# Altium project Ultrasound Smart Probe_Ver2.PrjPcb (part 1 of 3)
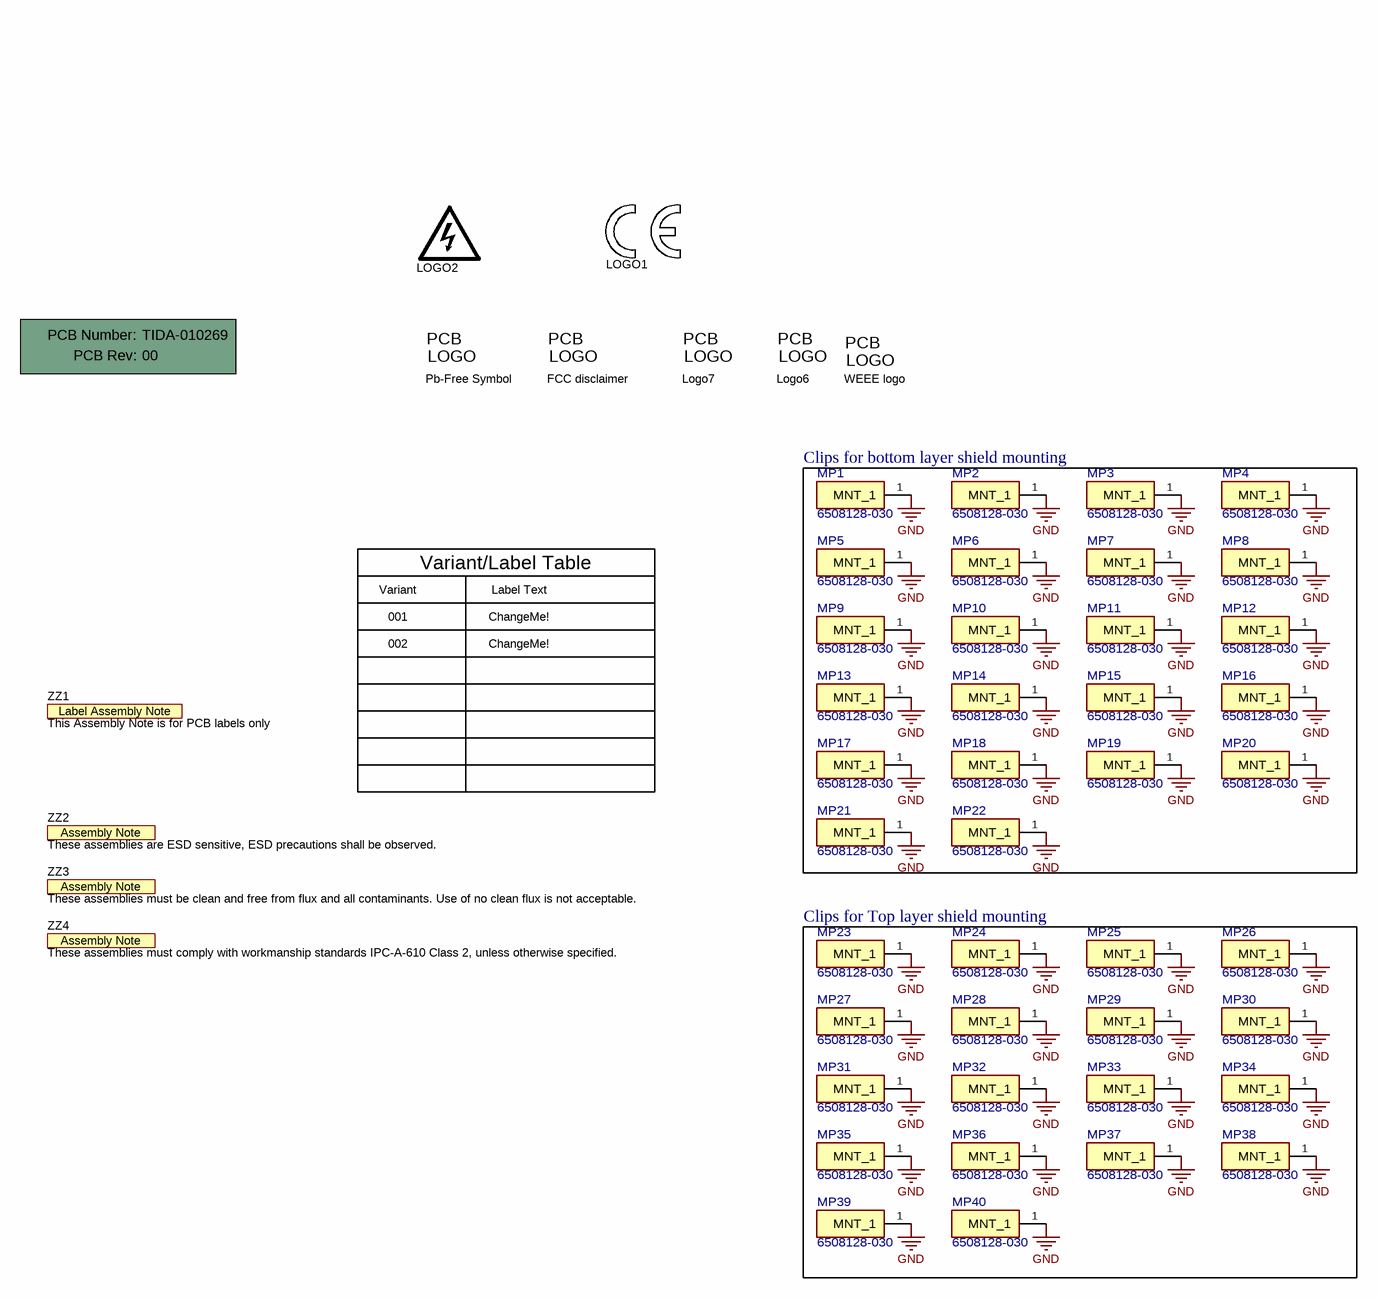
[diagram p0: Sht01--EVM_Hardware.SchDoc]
CopyrightYear: 2023; PCB_Layout: Bill.Xu; PCB_Rev: 00; PRJ_Customer: Public Release; PRJ_Engineer: Bill. Xu; PRJ_Number: TIDA-010269; PRJ_Title: Smart Probe Power Supply; SCH_Rev: 00; TechSupport: http://www.ti.com/support; TID: TIDA-010269
7 sheets, 486 parts. Net scope: flat (ports and power ports of the same name join across sheets).
Board file: TIDA-010269.PcbDoc
Sheets:
  Sht01--EVM_Hardware.SchDoc
  Sht02--Input Output Connector.SchDoc
  Sht03--Efuse_Power on-Off Controller.SchDoc
  Sht04--FPGA Power Supply.SchDoc
  Sht05--TX-RX Supply 1.8V and 1.15V.SchDoc
  Sht06--TX Supply +5V and -5V.SchDoc
  Sht07--High Voltage Power Supply.SchDoc

## Sheet Sht01--EVM_Hardware.SchDoc: Hardware
size 431 x 279 mm; Date: Not shown in title block; ApprovedBy: Not shown in title block; CheckedBy: Not shown in title block; Author: Not shown in title block; CompanyName: Not shown in title block; DrawnBy: Bill.Xu; Engineer: Bill.Xu; Organization: Not shown in title block; Address1: Not shown in title block; Address2: Not shown in title block; Address3: Not shown in title block; Address4: Not shown in title block; DocumentNumber: 1; Revision: Use project parameter SCH_Rev; SheetNumber: 1; SheetTotal: 7; PageSetup: Record=PageOptions¦CenterHorizontal=True¦CenterVertical=True¦PrintScale=1.00¦XCorrection=1.00¦YCorrection=1.00¦PrintKind=0¦BorderSize=5000000¦LeftOffset=0¦BottomOffset=0¦Orientation=2¦PaperLength=1000¦PaperWidth=1000¦Scale=100¦PaperSource=15¦PrintQuality=600¦MediaType=1¦DitherType=10¦PaperKind=Letter¦PrintScaleMode=1

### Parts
!PCB1  Printed Circuit Board  (value not drawn)  (mechanical)
LOGO1  CE Mark  [TI_Stacked_Overlay_Small]  (value not drawn)  (no BOM)
LOGO2  DANGER HIGH VOLTAGE  [CE_Mark_5mm]  (value not drawn)  (no BOM)
Logo3  Pb-Free Symbol  [FCC_disclaimer]  (no BOM)
Logo4  FCC disclaimer  [WEEE_Minimum]  (no BOM)
Logo5  WEEE logo  [WEEE_Minimum]  (no BOM)
Logo6  ESD Susceptible  [ESD_Overlay_Small]  (value not drawn)  (no BOM)
Logo7  Texas Instruments  [TI_Stacked_Overlay_Small]  (value not drawn)  (no BOM)
MP1  6508128-030  [0-MFG]
MP2  6508128-030  [0-MFG]
MP3  6508128-030  [0-MFG]
MP4  6508128-030  [0-MFG]
MP5  6508128-030  [0-MFG]
MP6  6508128-030  [0-MFG]
MP7  6508128-030  [0-MFG]
MP8  6508128-030  [0-MFG]
MP9  6508128-030  [0-MFG]
MP10  6508128-030  [0-MFG]
MP11  6508128-030  [0-MFG]
MP12  6508128-030  [0-MFG]
MP13  6508128-030  [0-MFG]
MP14  6508128-030  [0-MFG]
MP15  6508128-030  [0-MFG]
MP16  6508128-030  [0-MFG]
MP17  6508128-030  [0-MFG]
MP18  6508128-030  [0-MFG]
MP19  6508128-030  [0-MFG]
MP20  6508128-030  [0-MFG]
MP21  6508128-030  [0-MFG]
MP22  6508128-030  [0-MFG]
MP23  6508128-030  [0-MFG]
MP24  6508128-030  [0-MFG]
MP25  6508128-030  [0-MFG]
MP26  6508128-030  [0-MFG]
MP27  6508128-030  [0-MFG]
MP28  6508128-030  [0-MFG]
MP29  6508128-030  [0-MFG]
MP30  6508128-030  [0-MFG]
MP31  6508128-030  [0-MFG]
MP32  6508128-030  [0-MFG]
MP33  6508128-030  [0-MFG]
MP34  6508128-030  [0-MFG]
MP35  6508128-030  [0-MFG]
MP36  6508128-030  [0-MFG]
MP37  6508128-030  [0-MFG]
MP38  6508128-030  [0-MFG]
MP39  6508128-030  [0-MFG]
MP40  6508128-030  [0-MFG]
ZZ1  This Assembly Note is for PCB labels only  [AssemblyNoteLabel]  (no BOM)
ZZ2  These assemblies are ESD sensitive, ESD precautions shall be observed.  [AssemblyNote]  (no BOM)
ZZ3  These assemblies must be clean and free from flux and all contaminants. Use of no clean flux is not acceptable.  [AssemblyNote]  (no BOM)
ZZ4  These assemblies must comply with workmanship standards IPC-A-610 Class 2, unless otherwise specified.  [AssemblyNote]  (no BOM)

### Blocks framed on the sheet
Clips for bottom layer shield mounting: MP1-MP22
Clips for Top layer shield mounting: MP23-MP40

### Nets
GND: MP1.1(MNT_1) MP2.1(MNT_1) MP3.1(MNT_1) MP4.1(MNT_1) MP5.1(MNT_1) MP6.1(MNT_1) MP7.1(MNT_1) MP8.1(MNT_1) MP9.1(MNT_1) MP10.1(MNT_1) MP11.1(MNT_1) MP12.1(MNT_1) MP13.1(MNT_1) MP14.1(MNT_1) MP15.1(MNT_1) MP16.1(MNT_1) MP17.1(MNT_1) MP18.1(MNT_1) MP19.1(MNT_1) MP20.1(MNT_1) MP21.1(MNT_1) MP22.1(MNT_1) MP23.1(MNT_1) MP24.1(MNT_1) MP25.1(MNT_1) MP26.1(MNT_1) MP27.1(MNT_1) MP28.1(MNT_1) MP29.1(MNT_1) MP30.1(MNT_1) MP31.1(MNT_1) MP32.1(MNT_1) MP33.1(MNT_1) MP34.1(MNT_1) MP35.1(MNT_1) MP36.1(MNT_1) MP37.1(MNT_1) MP38.1(MNT_1) MP39.1(MNT_1) MP40.1(MNT_1)

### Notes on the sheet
- Variant/Label Table
- Variant
- 001
- 002
- Label Text
- ChangeMe!

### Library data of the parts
!PCB1 = PCB: Manufacturer: Any; PartNumber: TIDA-010269; SymbolCreator: a0412235
LOGO1 = CE Mark: SymbolCreator: a0412235
LOGO2 = IEC_HighVoltage: IEC 61010-1 High Voltage Warning; SymbolCreator: a0412235
Logo3 = Pb-Free: SymbolCreator: a0412235
Logo4 = FCC_disclaimer: SymbolCreator: a0412235
Logo5 = CMP-0074769-3: Manufacturer: Texas Instruments; Alternate Manufacturer: None; CompType: IC; AEC Category: Q200
Logo6 = ESD_Susceptible: ESD Susceptible Symbol; SymbolCreator: a0412235
Logo7 = TI_Logo: Texas Instrument Corporate Signature; SymbolCreator: a0412235
MP1-MP40 = CMP-0037144-1: SHIELD (T0.3) CAN CLIP L6.50*W0.8*H1.28mm; Manufacturer: Texas Instruments; SizeZ_mm: 1.38mm
ZZ1 = AssemblyNoteLabel: SymbolCreator: a0412235
ZZ2-ZZ4 = AssemblyNote: SymbolCreator: codlsc

## Sheet Sht02--Input Output Connector.SchDoc: Input Output Connectors
size 431 x 279 mm; Date: Not shown in title block; ApprovedBy: Not shown in title block; CheckedBy: Not shown in title block; Author: Not shown in title block; CompanyName: Not shown in title block; DrawnBy: Bill.Xu; Engineer: Bill.Xu; Organization: Not shown in title block; Address1: Not shown in title block; Address2: Not shown in title block; Address3: Not shown in title block; Address4: Not shown in title block; DocumentNumber: 1; Revision: Use project parameter SCH_Rev; SheetNumber: 2; SheetTotal: 7; PageSetup: Record=PageOptions¦CenterHorizontal=True¦CenterVertical=True¦PrintScale=1.00¦XCorrection=1.00¦YCorrection=1.00¦PrintKind=0¦BorderSize=5000000¦LeftOffset=0¦BottomOffset=0¦Orientation=2¦PaperLength=1000¦PaperWidth=1000¦Scale=100¦PaperSource=15¦PrintQuality=600¦MediaType=1¦DitherType=10¦PaperKind=Letter¦PrintScaleMode=1
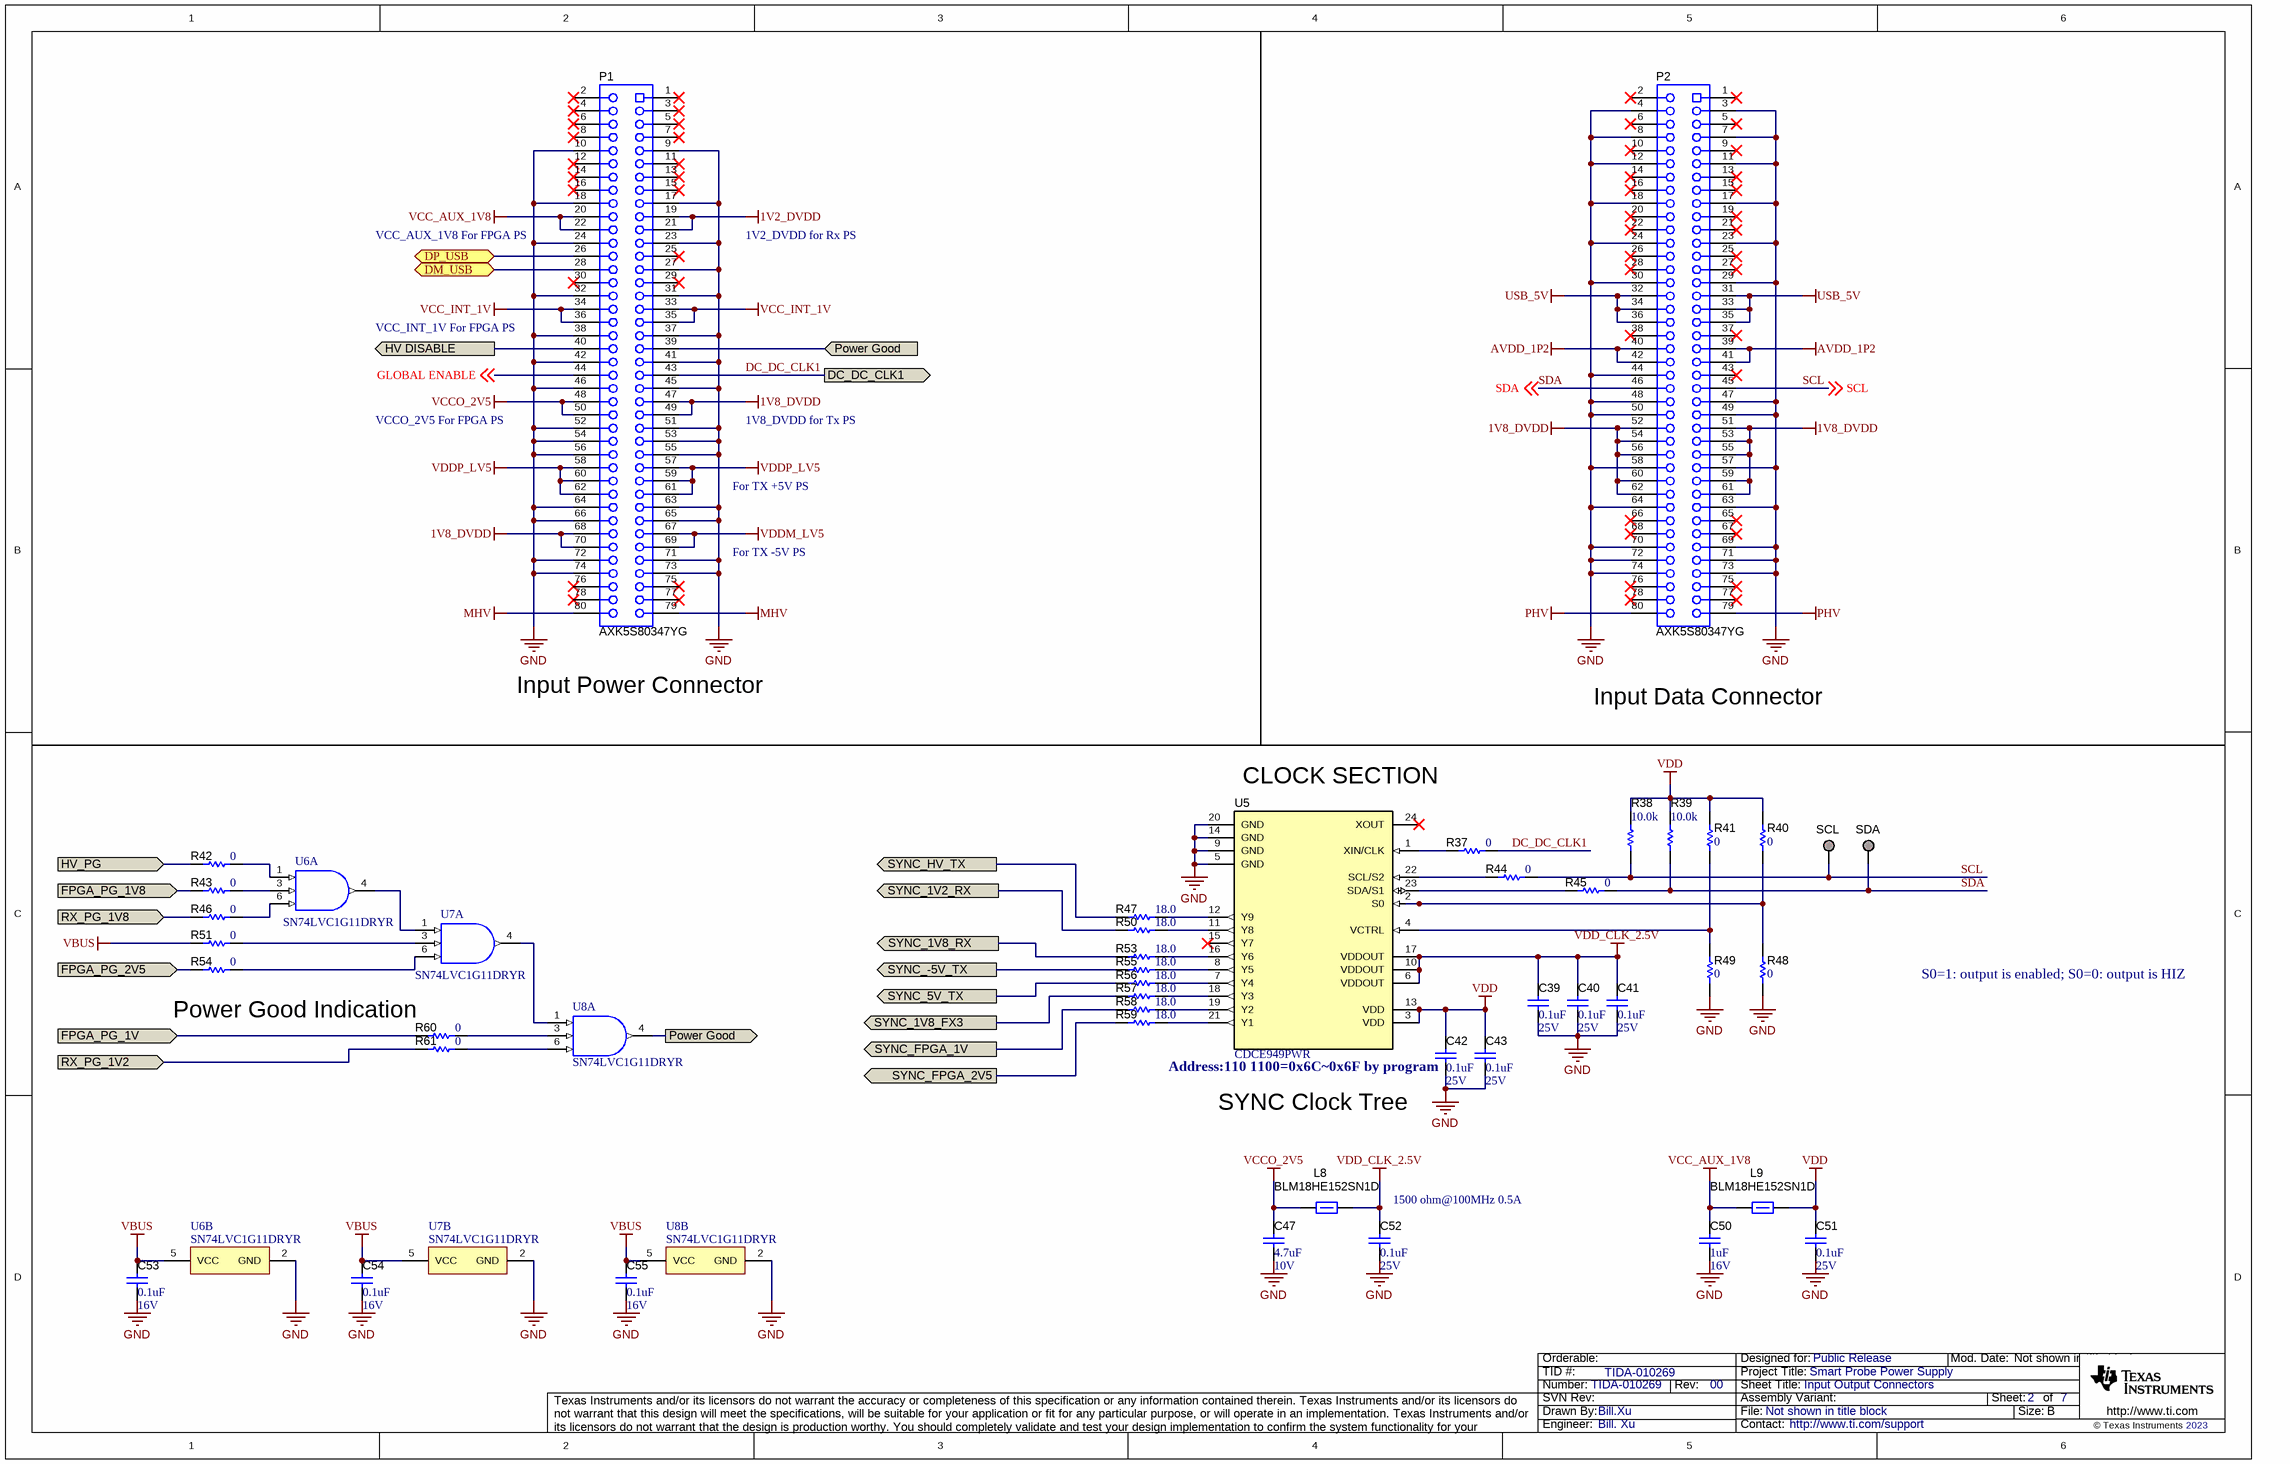
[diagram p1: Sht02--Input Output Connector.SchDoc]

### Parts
C39  VDC_V: 25V  ValueDisplayed: 0.1uF  [0402]  (hidden comment: GRM155R61E104KA87D)
C40  VDC_V: 25V  ValueDisplayed: 0.1uF  [0402]  (hidden comment: GRM155R61E104KA87D)
C41  VDC_V: 25V  ValueDisplayed: 0.1uF  [0402]  (hidden comment: GRM155R61E104KA87D)
C42  VDC_V: 25V  ValueDisplayed: 0.1uF  [0402]  (hidden comment: GRM155R61E104KA87D)
C43  VDC_V: 25V  ValueDisplayed: 0.1uF  [0402]  (hidden comment: GRM155R61E104KA87D)
C47  VDC_V: 10V  ValueDisplayed: 4.7uF  [0603]  (hidden comment: GRM188R61A475MAAJ)
C50  VDC_V: 16V  ValueDisplayed: 1uF  [0402]  (hidden comment: C1005X6S1C105K050BC)
C51  VDC_V: 25V  ValueDisplayed: 0.1uF  [0402]  (hidden comment: GRM155R61E104KA87D)
C52  VDC_V: 25V  ValueDisplayed: 0.1uF  [0402]  (hidden comment: GRM155R61E104KA87D)
C53  VDC_V: 16V  ValueDisplayed: 0.1uF  [0201_033]  (hidden comment: C0603X6S1C104K030BC)
C54  VDC_V: 16V  ValueDisplayed: 0.1uF  [0201_033]  (hidden comment: C0603X6S1C104K030BC)
C55  VDC_V: 16V  ValueDisplayed: 0.1uF  [0201_033]  (hidden comment: C0603X6S1C104K030BC)
L8  BLM18HE152SN1D  [0603]
L9  BLM18HE152SN1D  [0603]
P1  AXK5S80347YG  [Panasonic_AXK5S80347Y]
P2  AXK5S80347YG  [Panasonic_AXK5S80347Y]
R37  ValueDisplayed: 0  [0201]  (hidden comment: CRCW02010000Z0ED)
R38  ValueDisplayed: 10.0k  [0201]  (hidden comment: RC0201FS-7D10KL)
R39  ValueDisplayed: 10.0k  [0201]  (hidden comment: RC0201FS-7D10KL)
R40  ValueDisplayed: 0  [0201]  (hidden comment: CRCW02010000Z0ED)
R41  ValueDisplayed: 0  [0201]  (hidden comment: CRCW02010000Z0ED)
R42  ValueDisplayed: 0  [0201]  (hidden comment: CRCW02010000Z0ED)
R43  ValueDisplayed: 0  [0201]  (hidden comment: CRCW02010000Z0ED)
R44  ValueDisplayed: 0  [0201]  (hidden comment: CRCW02010000Z0ED)
R45  ValueDisplayed: 0  [0201]  (hidden comment: CRCW02010000Z0ED)
R46  ValueDisplayed: 0  [0201]  (hidden comment: CRCW02010000Z0ED)
R47  ValueDisplayed: 18.0  [0201]  (hidden comment: RC0201FR-0718RL)
R48  ValueDisplayed: 0  [0201]  (hidden comment: CRCW02010000Z0ED)
R49  ValueDisplayed: 0  [0201]  (hidden comment: CRCW02010000Z0ED)
R50  ValueDisplayed: 18.0  [0201]  (hidden comment: RC0201FR-0718RL)
R51  ValueDisplayed: 0  [0201]  (hidden comment: CRCW02010000Z0ED)
R53  ValueDisplayed: 18.0  [0201]  (hidden comment: RC0201FR-0718RL)
R54  ValueDisplayed: 0  [0201]  (hidden comment: CRCW02010000Z0ED)
R55  ValueDisplayed: 18.0  [0201]  (hidden comment: RC0201FR-0718RL)
R56  ValueDisplayed: 18.0  [0201]  (hidden comment: RC0201FR-0718RL)
R57  ValueDisplayed: 18.0  [0201]  (hidden comment: RC0201FR-0718RL)
R58  ValueDisplayed: 18.0  [0201]  (hidden comment: RC0201FR-0718RL)
R59  ValueDisplayed: 18.0  [0201]  (hidden comment: RC0201FR-0718RL)
R60  ValueDisplayed: 0  [0201]  (hidden comment: CRCW02010000Z0ED)
R61  ValueDisplayed: 0  [0201]  (hidden comment: CRCW02010000Z0ED)
SCL  TESTPOINT  [TESTPOINT]  (value not drawn)  (no BOM)
SDA  TESTPOINT  [TESTPOINT]  (value not drawn)  (no BOM)
U5  CDCE949PWR  [PW0024A_N]
U6  SN74LVC1G11DRYR  [DRY0006A]  (parts A,B of 2)
U7  SN74LVC1G11DRYR  [DRY0006A]  (parts A,B of 2)
U8  SN74LVC1G11DRYR  [DRY0006A]  (parts A,B of 2)

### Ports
DC_DC_CLK1 (out), DM_USB (bidir), DP_USB (bidir), FPGA_PG_1V8 (in), FPGA_PG_1V (in), FPGA_PG_2V5 (in), HV DISABLE (out), HV_PG (in), Power Good (in), Power Good (out), RX_PG_1V2 (in), RX_PG_1V8 (in), SYNC_1V2_RX (out), SYNC_1V8_FX3 (out), SYNC_1V8_RX (out), SYNC_5V_TX (out), SYNC_-5V_TX (out), SYNC_FPGA_1V (out), SYNC_FPGA_2V5 (out), SYNC_HV_TX (out)

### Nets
1V2_DVDD: P1.19 P1.21
1V8_DVDD: P1.47 P1.49 P1.68 P1.70 P2.51 P2.52 P2.53 P2.54 P2.55 P2.56 P2.59 P2.60 P2.61 P2.62
AVDD_1P2: P2.39 P2.40 P2.41 P2.42
GND: C39.2 C40.2 C41.2 C42.2 C43.2 C47.2 C50.2 C51.2 C52.2 C53.2 C54.2 C55.2 P1.9 P1.10 P1.17 P1.18 P1.23 P1.24 P1.27 P1.31 P1.32 P1.37 P1.38 P1.41 P1.42 P1.45 P1.46 P1.51 P1.52 P1.53 P1.54 P1.55 P1.56 P1.63 P1.64 P1.65 P1.66 P1.71 P1.72 P1.73 P1.74 P2.3 P2.4 P2.7 P2.8 P2.11 P2.12 P2.17 P2.18 P2.23 P2.24 P2.29 P2.30 P2.44 P2.47 P2.48 P2.49 P2.50 P2.57 P2.58 P2.63 P2.64 P2.69 P2.70 P2.71 P2.72 P2.73 P2.74 R48.2 R49.2 U5.5(GND) U5.9(GND) U5.14(GND) U5.20(GND) U6.2(GND) U7.2(GND) U8.2(GND)
MHV: P1.79 P1.80
PHV: P2.79 P2.80
USB_5V: P2.31 P2.32 P2.33 P2.34 P2.35 P2.36
VBUS: C53.1 C54.1 C55.1 R51.1 U6.5(VCC) U7.5(VCC) U8.5(VCC)
VCC_AUX_1V8: C50.1 L9.1 P1.20 P1.22
VCC_INT_1V: P1.33 P1.34 P1.35 P1.36
VCCO_2V5: C47.1 L8.1 P1.48 P1.50
VDD: C42.1 C43.1 C51.1 L9.2 R38.2 R39.2 R40.2 R41.2 U5.3(VDD) U5.13(VDD)
VDD_CLK_2.5V: C39.1 C40.1 C41.1 C52.1 L8.2 U5.6(VDDOUT) U5.10(VDDOUT) U5.17(VDDOUT)
VDDM_LV5: P1.67 P1.69
VDDP_LV5: P1.57 P1.58 P1.59 P1.60 P1.61 P1.62
DC_DC_CLK1: P1.43 R37.2 ; port DC_DC_CLK1
DM_USB: P1.28 ; port DM_USB
DP_USB: P1.26 ; port DP_USB
FPGA_PG_1V: R60.1 ; port FPGA_PG_1V
FPGA_PG_1V8: R43.1 ; port FPGA_PG_1V8
FPGA_PG_2V5: R54.1 ; port FPGA_PG_2V5
GLOBAL ENABLE: P1.44 ; off-sheet GLOBAL ENABLE
HV DISABLE: P1.40 ; port HV DISABLE
HV_PG: R42.1 ; port HV_PG
Power Good: P1.39 U8.4(Y) ; port Power Good
RX_PG_1V2: R61.1 ; port RX_PG_1V2
RX_PG_1V8: R46.1 ; port RX_PG_1V8
SCL: P2.45 R38.1 R44.2 SCL.1 ; off-sheet SCL
SDA: P2.46 R39.1 R45.2 SDA.1 ; off-sheet SDA
SYNC_1V2_RX: R50.1 ; port SYNC_1V2_RX
SYNC_1V8_FX3: R57.1 ; port SYNC_1V8_FX3
SYNC_1V8_RX: R53.1 ; port SYNC_1V8_RX
SYNC_5V_TX: R56.1 ; port SYNC_5V_TX
SYNC_-5V_TX: R55.1 ; port SYNC_-5V_TX
SYNC_FPGA_1V: R58.1 ; port SYNC_FPGA_1V
SYNC_FPGA_2V5: R59.1 ; port SYNC_FPGA_2V5
SYNC_HV_TX: R47.1 ; port SYNC_HV_TX
NetR37_1: R37.1 U5.1(XIN/CLK)
NetR40_1: R40.1 R48.1 U5.2(S0)
NetR41_1: R41.1 R49.1 U5.4(VCTRL)
NetR42_2: R42.2 U6.1(A)
NetR43_2: R43.2 U6.3(B)
NetR44_1: R44.1 U5.22(SCL/S2)
NetR45_1: R45.1 U5.23(SDA/S1)
NetR46_2: R46.2 U6.6(C)
NetR47_2: R47.2 U5.12(Y9)
NetR50_2: R50.2 U5.11(Y8)
NetR51_2: R51.2 U7.3(B)
NetR53_2: R53.2 U5.16(Y6)
NetR54_2: R54.2 U7.6(C)
NetR55_2: R55.2 U5.8(Y5)
NetR56_2: R56.2 U5.7(Y4)
NetR57_2: R57.2 U5.18(Y3)
NetR58_2: R58.2 U5.19(Y2)
NetR59_2: R59.2 U5.21(Y1)
NetR60_2: R60.2 U8.3(B)
NetR61_2: R61.2 U8.6(C)
NetU6_4: U6.4(Y) U7.1(A)
NetU7_4: U7.4(Y) U8.1(A)

Not connected (* = marked no-connect by the designer): P1 1* 2* 3* 4* 5* 6* 7* 8* 11* 12* 13* 14* 15* 16* 25* 29* 30* 75* 76* 77* 78*; P2 1* 2* 5* 6* 9* 10* 13* 14* 15* 16* 19* 20* 21* 22* 25* 26* 27* 28* 37* 38* 43* 65* 66* 67* 68* 75* 76* 77* 78*; U5 15(Y7)* 24(XOUT)*

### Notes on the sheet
- VCC_AUX_1V8 For FPGA PS
- 1V2_DVDD for Rx PS
- VCC_INT_1V For FPGA PS
- VCCO_2V5 For FPGA PS
- 1V8_DVDD for Tx PS
- For TX +5V PS
- For TX -5V PS
- Input Power Connector
- Input Data Connector
- (near U5) CLOCK SECTION
- Power Good Indication
- S0=1: output is enabled; S0=0: output is HIZ
- (near C42) Address:110 1100=0x6C~0x6F by program
- SYNC Clock Tree
- (near C52) 1500 ohm@100MHz 0.5A

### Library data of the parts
C39 C40 C43 C51 C52 = CMP-0006607-1: CAP, CERM, 0.1 uF, 25 V, +/- 10%, X5R, 0402; Manufacturer: MuRata; TaMin_C: -55°C; Polarized: N; SizeAreaWB_mm2: 3; Value1: Unknown; U/M: EA; Value: 0.1uF; TaMax_C: 85°C; SizeZ_mm: 0.6; SizeX_mm: 1; SizeY_mm: 0.5; Cap_F: 100nF; AEC Category: Q200
C41 C42 = CMP-0006607-2: CAP, CERM, 0.1 uF, 25 V, +/- 10%, X5R, 0402; Manufacturer: MuRata; TaMin_C: -55°C; Polarized: N; SizeAreaWB_mm2: 3; Value1: Unknown; U/M: EA; Value: 0.1uF; TaMax_C: 85°C; SizeZ_mm: 0.6; SizeX_mm: 1; SizeY_mm: 0.5; Cap_F: 100nF; AEC Category: Q200
C47 = CMP-0007329-4: CAP, CERM, 4.7 uF, 10 V, +/- 20%, X5R, 0603; Manufacturer: MuRata; TaMin_C: -55°C; Polarized: N; SizeAreaWB_mm2: 4.68; Value1: Unknown; U/M: EA; Value: 4.7uF; TaMax_C: 85°C; SizeZ_mm: 1; SizeX_mm: 1.6; SizeY_mm: 0.8; SizeArea_mm2: 1.28; Cap_F: 4.7µF; AEC Category: Q200
C50 = CMP-0006286-1: CAP, CERM, 1 uF, 16 V, +/- 10%, X6S, 0402; Manufacturer: TDK; TaMin_C: -55°C; ESR_ohm: 11.416m; Polarized: N; SizeAreaWB_mm2: 3; Value1: 0.011416 ohm; U/M: EA; Value: 1uF; TaMax_C: 105°C; SizeZ_mm: 0.6; SizeX_mm: 1; SizeY_mm: 0.5; Cap_F: 1µF; IRMS_A: 1.483A; AEC Category: Q200
C53-C55 = CMP-0009637-1: CAP, CERM, 0.1 uF, 16 V, +/- 10%, X6S, 0201; Manufacturer: TDK; TaMin_C: -55°C; Polarized: N; SizeAreaWB_mm2: 2.08; Value1: Unknown; U/M: EA; Value: 0.1uF; TaMax_C: 105°C; SizeZ_mm: 0.33; SizeX_mm: 0.6; SizeY_mm: 0.3; Cap_Case: 0201; SizeArea_mm2: 0.18; Cap_F: 100nF; AEC Category: Q200
L8 = CMP-0003349-2: Ferrite Bead, 1500 ohm @ 100 MHz, 0.5 A, 0603; Manufacturer: MuRata; Ztyp@1GHz_Ohm: 1.5k; SizeAreaWB_mm2: 4.68; DCR_ohm: 0.5; Value1: 0.5 ohm; Imax_A: 500mA; SizeZ_mm: 1; SizeX_mm: 1.6; SizeY_mm: 0.8; Value2: 0.5A; SizeArea_mm2: 1.28
L9 = CMP-0003349-1: Ferrite Bead, 1500 ohm @ 100 MHz, 0.5 A, 0603; Manufacturer: MuRata; Ztyp@1GHz_Ohm: 1.5k; SizeAreaWB_mm2: 4.68; DCR_ohm: 0.5; Value1: 0.5 ohm; Imax_A: 500mA; SizeZ_mm: 1; SizeX_mm: 1.6; SizeY_mm: 0.8; Value2: 0.5A; SizeArea_mm2: 1.28
P1 P2 = CMP-0084862-1: Receptacle, 0.5mm, 40x2, Gold, SMD; Manufacturer: Panasonic; RowSpacing_mm: 4.4; Row_Count: 2; Pitch_mm: 0.5; Gender: Female; CompType: Socket Strip
R37 R40-R46 R48 R49 R51 R54 R60 R61 = CMP-0027008-1: RES, 0, 5%, 0.05 W, 0201; Manufacturer: Vishay-Dale; Power_W: 50mW; TempCo: ppm/C; Value_Code: 0000; U/M: EA; Value: 0; EIA_Code: E24; SizeX_mm: 0.6; SizeY_mm: 0.3; SizeZ_mm: 0.26; Value2: 0.05W; SizeArea_mm2: 0.18; AEC Qualified: N; AEC Category: Q200
R38 R39 = CMP-0028071-1: RES SMD 10K OHM 1% 1/20W 0201; Manufacturer: Samsung Electro-Mechanics; PartNumber: RC0603F103CS; Power_W: 50mW; TempCo: 200 ppm/C; Value_Code: 10k0; U/M: EA; Value: 10.0k; EIA_Code: E96; SizeX_mm: 0.6; SizeY_mm: 0.3; SizeZ_mm: 0.26; Value2: 0.05W; SizeArea_mm2: 0.18; AEC Qualified: N; VDC_V: 25V; AEC Category: Q200
R47 R50 R53 R55-R59 = CMP-0027413-1: RES, 18.0, 1%, 0.05 W, 0201; Manufacturer: Yageo America; Power_W: 50mW; TempCo: 200 ppm/C; Value_Code: 18R0; U/M: EA; Value: 18.0; Res_ohm: 18; SizeX_mm: 0.6; SizeY_mm: 0.3; SizeZ_mm: 0.26; Value2: 0.05W; SizeArea_mm2: 0.18; AEC Qualified: N; VDC_V: 25V; AEC Category: Q200
SCL SDA = CMP-0078143-2: TEST POINT.  No entry in BOM.
U5 = CMP-0075866-2: Programmable 4-PLL VCXO Clock Synthesizer with 2.5V or 3.3V LVCMOS Outputs, PW0024A (TSSOP-24); Manufacturer: Texas Instruments; SizeAreaWB_mm2: 82.32; SizeArea_mm2: 49.92; SizeZ_mm: 1.2; SizeY_mm: 7.8; CompType: IC; SizeX_mm: 6.4; AEC Category: Q200; AEC Qualified: N; Rating: Catalog
U6-U8 = CMP-0051217-4: Single 3-Input Positive-AND Gate, DRY0006A (USON-6); Manufacturer: Texas Instruments; Output Type: CMOS; Bits(#): 1; Input Type: CMOS/TTL; Technology Family: LVC; Schmitt Trigger: No; VCC(Max)(V): 5.5; Gate Type: AND; Rating: Catalog; Output Drive (IOL/IOH)(Max)(mA): 32/-32; ICC @ Nom Voltage(Max)(mA): 0.01; VCC(Min)(V): 1.65; F @ Nom Voltage(Max)(Mhz): 150; Logic: True; Voltage(Nom)(V): 1.8,2.5,3.3,5; tpd @ Nom Voltage(Max)(ns): 20,7.8,6.2,4.6; AEC Category: Q200; AEC Qualified: N; CompType: IC; SizeAreaWB_mm2: 4.9; SizeArea_mm2: 1.45; SizeX_mm: 1.0; SizeZ_mm: 0.6

## Sheet Sht03--Efuse_Power on-Off Controller.SchDoc: Efuse Charger Power On-Off
size 431 x 279 mm; Date: Not shown in title block; ApprovedBy: Not shown in title block; CheckedBy: Not shown in title block; Author: Not shown in title block; CompanyName: Not shown in title block; DrawnBy: Bill.Xu; Engineer: Bill.Xu; Organization: Not shown in title block; Address1: Not shown in title block; Address2: Not shown in title block; Address3: Not shown in title block; Address4: Not shown in title block; DocumentNumber: 1; Revision: Use project parameter SCH_Rev; SheetNumber: 3; SheetTotal: 7; PageSetup: Record=PageOptions¦CenterHorizontal=True¦CenterVertical=True¦PrintScale=1.00¦XCorrection=1.00¦YCorrection=1.00¦PrintKind=0¦BorderSize=5000000¦LeftOffset=0¦BottomOffset=0¦Orientation=2¦PaperLength=1000¦PaperWidth=1000¦Scale=100¦PaperSource=15¦PrintQuality=600¦MediaType=1¦DitherType=10¦PaperKind=Letter¦PrintScaleMode=1
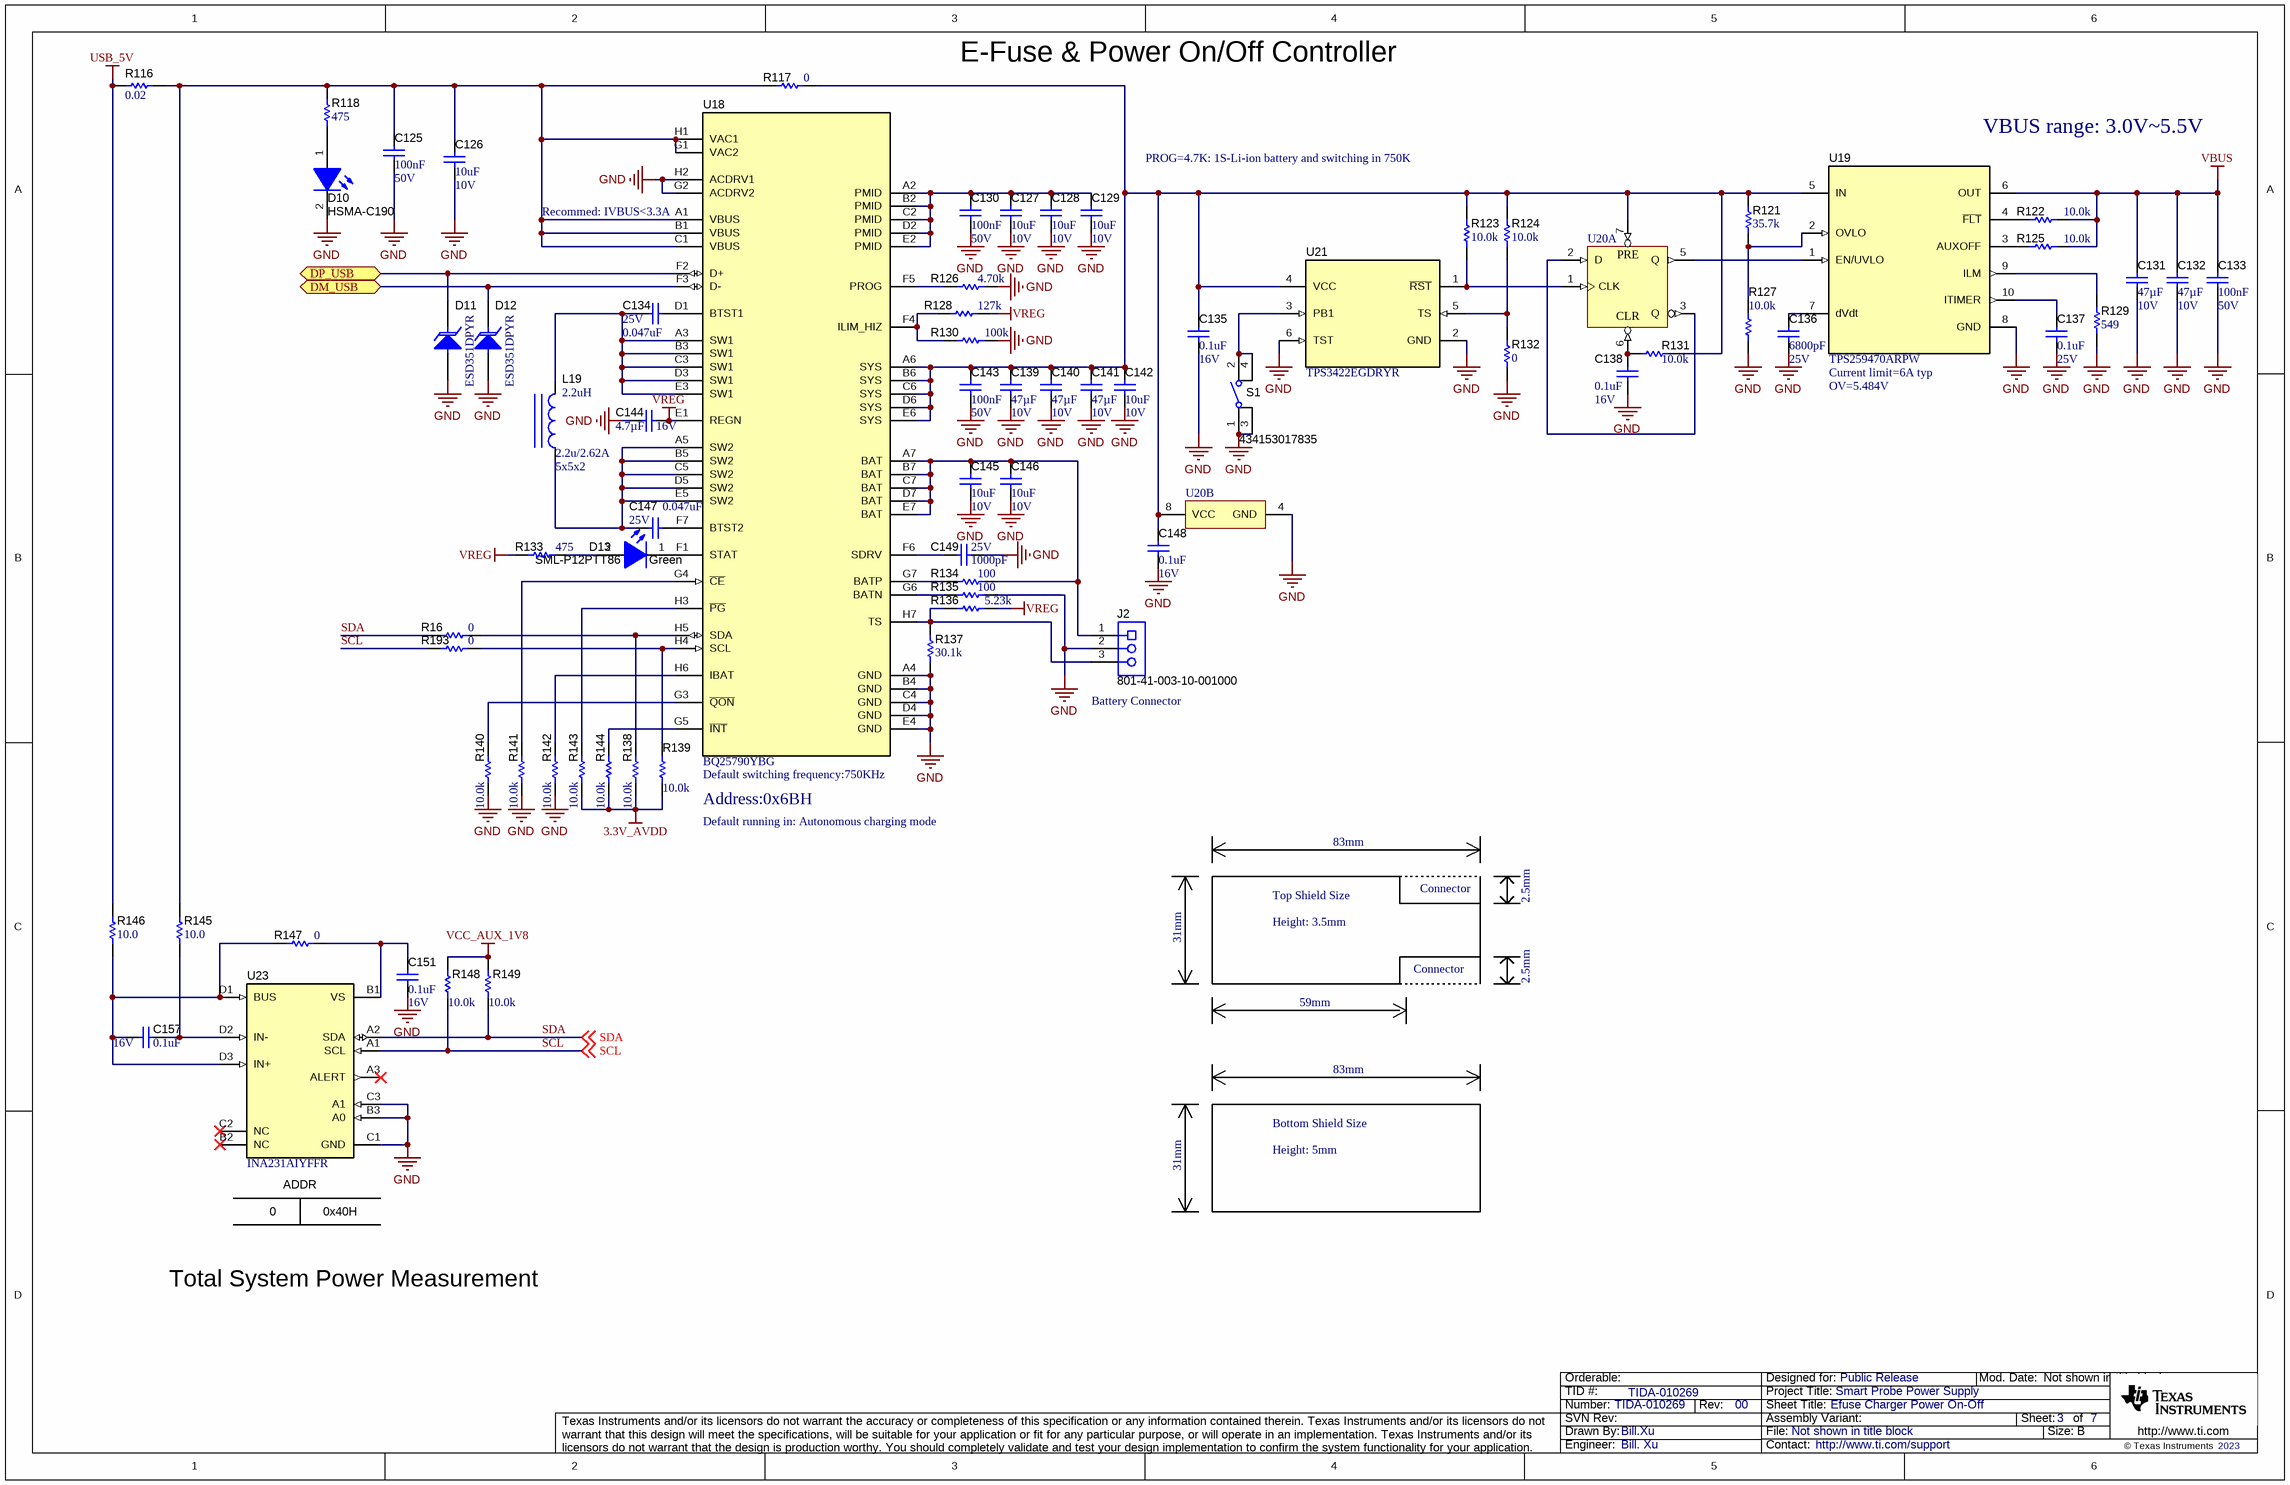
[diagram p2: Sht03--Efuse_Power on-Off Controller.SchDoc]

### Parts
C125  Cap_F: 100nF  VDC_V: 50V  [0603]  (hidden comment: 885012206095)
C126  VDC_V: 10V  ValueDisplayed: 10uF  [0805_HV]  (hidden comment: GRM21BC81A106KE18L)
C127  VDC_V: 10V  ValueDisplayed: 10uF  [0805_HV]  (hidden comment: GRM21BC81A106KE18L)
C128  VDC_V: 10V  ValueDisplayed: 10uF  [0805_HV]  (hidden comment: GRM21BC81A106KE18L)
C129  VDC_V: 10V  ValueDisplayed: 10uF  [0805_HV]  (hidden comment: GRM21BC81A106KE18L)
C130  Cap_F: 100nF  VDC_V: 50V  [0603]  (hidden comment: 885012206095)
C131  VDC_V: 10V  ValueDisplayed: 47µF  [0805_HV]  (hidden comment: GRM21BR61A476ME15L)
C132  VDC_V: 10V  ValueDisplayed: 47µF  [0805_HV]  (hidden comment: GRM21BR61A476ME15L)
C133  Cap_F: 100nF  VDC_V: 50V  [0603]  (hidden comment: 885012206095)
C134  VDC_V: 25V  ValueDisplayed: 0.047uF  [0402]  (hidden comment: GRM155R71E473KA88D)
C135  VDC_V: 16V  ValueDisplayed: 0.1uF  [0201_033]  (hidden comment: C0603X6S1C104K030BC)
C136  VDC_V: 25V  ValueDisplayed: 6800pF  [0402]  (hidden comment: GRM155R71E682KA01D)
C137  VDC_V: 25V  ValueDisplayed: 0.1uF  [0402]  (hidden comment: GRM155R61E104KA87D)
C138  VDC_V: 16V  ValueDisplayed: 0.1uF  [0201_033]  (hidden comment: C0603X6S1C104K030BC)
C139  VDC_V: 10V  ValueDisplayed: 47µF  [0805_HV]  (hidden comment: GRM21BR61A476ME15L)
C140  VDC_V: 10V  ValueDisplayed: 47µF  [0805_HV]  (hidden comment: GRM21BR61A476ME15L)
C141  VDC_V: 10V  ValueDisplayed: 47µF  [0805_HV]  (hidden comment: GRM21BR61A476ME15L)
C142  VDC_V: 10V  ValueDisplayed: 10uF  [0805_HV]  (hidden comment: GRM21BC81A106KE18L)
C143  Cap_F: 100nF  VDC_V: 50V  [0603]  (hidden comment: 885012206095)
C144  VDC_V: 16V  ValueDisplayed: 4.7µF  [0603]  (hidden comment: GRT188R61C475KE13D)
C145  VDC_V: 10V  ValueDisplayed: 10uF  [0805_HV]  (hidden comment: GRM21BC81A106KE18L)
C146  VDC_V: 10V  ValueDisplayed: 10uF  [0805_HV]  (hidden comment: GRM21BC81A106KE18L)
C147  VDC_V: 25V  ValueDisplayed: 0.047uF  [0402]  (hidden comment: GRM155R71E473KA88D)
C148  VDC_V: 16V  ValueDisplayed: 0.1uF  [0201_033]  (hidden comment: C0603X6S1C104K030BC)
C149  VDC_V: 25V  ValueDisplayed: 1000pF  [0603]  (hidden comment: C0603C102F3GACTU)
C151  VDC_V: 16V  ValueDisplayed: 0.1uF  [0201_033]  (hidden comment: C0603X6S1C104K030BC)
C157  VDC_V: 16V  ValueDisplayed: 0.1uF  [0201_033]  (hidden comment: C0603X6S1C104K030BC)
D10  HSMA-C190  [HSMx-C190_Amber]
D11  ESD351DPYR  [DPY0002A]
D12  ESD351DPYR  [DPY0002A]
D13  SML-P12PTT86  value Green  [SML-P1_GREEN]
J2  801-41-003-10-001000  [Mill-Max_801-41-003-10-001000]
L19  ValueDisplayed: 2.2uH  [VLCF5020]  (hidden comment: VLCF5020T-2R2N2R6-3)
R16  ValueDisplayed: 0  [0201]  (hidden comment: CRCW02010000Z0ED)
R116  ValueDisplayed: 0.02  [WSLP0805]  (hidden comment: WSLP0805R0200FEB)
R117  ValueDisplayed: 0  [0805_HV]  (hidden comment: RC0805JR-070RL)
R118  ValueDisplayed: 475  [0402]  (hidden comment: CRCW0402475RFKED)
R121  ValueDisplayed: 35.7k  [0201]  (hidden comment: RC0201FR-0735K7L)
R122  ValueDisplayed: 10.0k  [0201]  (hidden comment: RC0201FS-7D10KL)
R123  ValueDisplayed: 10.0k  [0201]  (hidden comment: RC0201FS-7D10KL)
R124  ValueDisplayed: 10.0k  [0201]  (hidden comment: RC0201FS-7D10KL)
R125  ValueDisplayed: 10.0k  [0201]  (hidden comment: RC0201FS-7D10KL)
R126  ValueDisplayed: 4.70k  [0201]  (hidden comment: RC0201FR-7D4K7L)
R127  ValueDisplayed: 10.0k  [0201]  (hidden comment: RC0201FS-7D10KL)
R128  ValueDisplayed: 127k  [0201]  (hidden comment: RC0201FR-07127KL)
R129  ValueDisplayed: 549  [0402]  (hidden comment: CRCW0402549RFKED)
R130  ValueDisplayed: 100k  [0201]  (hidden comment: RC0201FR-7D100KL)
R131  ValueDisplayed: 10.0k  [0201]  (hidden comment: RC0201FS-7D10KL)
R132  ValueDisplayed: 0  [0201]  (hidden comment: CRCW02010000Z0ED)
R133  ValueDisplayed: 475  [0402]  (hidden comment: CRCW0402475RFKED)
R134  ValueDisplayed: 100  [0402]  (hidden comment: CRCW0402100RJNED)
R135  ValueDisplayed: 100  [0402]  (hidden comment: CRCW0402100RJNED)
R136  ValueDisplayed: 5.23k  [0201]  (hidden comment: RC0201FR-075K23L)
R137  ValueDisplayed: 30.1k  [0201]  (hidden comment: RC0201FR-0730K1L)
R138  ValueDisplayed: 10.0k  [0201]  (hidden comment: RC0201FS-7D10KL)
R139  ValueDisplayed: 10.0k  [0201]  (hidden comment: RC0201FS-7D10KL)
R140  ValueDisplayed: 10.0k  [0201]  (hidden comment: RC0201FS-7D10KL)
R141  ValueDisplayed: 10.0k  [0201]  (hidden comment: RC0201FS-7D10KL)
R142  ValueDisplayed: 10.0k  [0201]  (hidden comment: RC0201FS-7D10KL)
R143  ValueDisplayed: 10.0k  [0201]  (hidden comment: RC0201FS-7D10KL)
R144  ValueDisplayed: 10.0k  [0201]  (hidden comment: RC0201FS-7D10KL)
R145  ValueDisplayed: 10.0  [0201]  (hidden comment: RC0201FR-7D10RL)
R146  ValueDisplayed: 10.0  [0201]  (hidden comment: RC0201FR-7D10RL)
R147  ValueDisplayed: 0  [0201]  (hidden comment: CRCW02010000Z0ED)
R148  ValueDisplayed: 10.0k  [0201]  (hidden comment: RC0201FS-7D10KL)
R149  ValueDisplayed: 10.0k  [0201]  (hidden comment: RC0201FS-7D10KL)
R193  ValueDisplayed: 0  [0201]  (hidden comment: CRCW02010000Z0ED)
S1  434153017835  [SW_434153017835]
U18  BQ25790YBG  [PREYBG0056]
U19  TPS259470ARPW  [RPW0010A]
U20  SN74LVC1G74DQER  [DQE0008A]  (value not drawn)  (parts A,B of 2)
U21  TPS3422EGDRYR  [DRY0006A]
U23  INA231AIYFFR  [YFF0012AKAD]

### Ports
DM_USB (bidir), DP_USB (bidir)

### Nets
3.3V_AVDD: R138.1 R139.1 R143.1 R144.1
GND: C125.2 C126.2 C127.2 C128.2 C129.2 C130.2 C131.2 C132.2 C133.2 C135.2 C136.2 C137.2 C138.2 C139.2 C140.2 C141.2 C142.2 C143.2 C144.2 C145.2 C146.2 C148.2 C149.1 C151.2 D10.2(K) D11.2(A) D12.2(A) J2.2 R126.2 R127.2 R129.1 R130.2 R132.1 R135.2 R137.1 R140.1 R141.1 R142.1 S1.1 S1.3 U18.A4(GND) U18.B4(GND) U18.C4(GND) U18.D4(GND) U18.E4(GND) U18.G2(ACDRV2) U18.H2(ACDRV1) U19.8(GND) U20.4(GND) U21.2(GND) U21.6(TST) U23.B3(A0) U23.C1(GND) U23.C3(A1)
USB_5V: R116.1 R146.2
VBUS: C131.1 C132.1 C133.1 R122.1 R125.1 U19.6(OUT)
VCC_AUX_1V8: R148.2 R149.2
VREG: C144.1 R128.2 R133.2 R136.2 U18.E1(REGN)
DM_USB: D12.1(K) U18.F3(D-) ; port DM_USB
DP_USB: D11.1(K) U18.F2(D+) ; port DP_USB
SCL: R148.1 R193.1 U23.A1(SCL) ; off-sheet SCL
SDA: R16.1 R149.1 U23.A2(SDA) ; off-sheet SDA
NetC125_1: C125.1 C126.1 R116.2 R117.1 R118.2 R145.2 U18.A1(VBUS) U18.B1(VBUS) U18.C1(VBUS) U18.G1(VAC2) U18.H1(VAC1)
NetC127_1: C127.1 C128.1 C129.1 C130.1 U18.A2(PMID) U18.B2(PMID) U18.C2(PMID) U18.D2(PMID) U18.E2(PMID)
NetC134_1: C134.1 U18.D1(BTST1)
NetC134_2: C134.2 L19.2 U18.A3(SW1) U18.B3(SW1) U18.C3(SW1) U18.D3(SW1) U18.E3(SW1)
NetC135_1: C135.1 C139.1 C140.1 C141.1 C142.1 C143.1 C148.1 R117.2 R121.2 R123.2 R124.1 R131.1 U18.A6(SYS) U18.B6(SYS) U18.C6(SYS) U18.D6(SYS) U18.E6(SYS) U19.5(IN) U20.7(~{PRE}) U20.8(VCC) U21.4(VCC)
NetC136_1: C136.1 U19.7(dVdt)
NetC137_1: C137.1 U19.10(ITIMER)
NetC138_1: C138.1 R131.2 U20.6(~{CLR})
NetC145_1: C145.1 C146.1 J2.1 R134.2 U18.A7(BAT) U18.B7(BAT) U18.C7(BAT) U18.D7(BAT) U18.E7(BAT)
NetC147_1: C147.1 U18.F7(BTST2)
NetC147_2: C147.2 L19.1 U18.A5(SW2) U18.B5(SW2) U18.C5(SW2) U18.D5(SW2) U18.E5(SW2)
NetC149_2: C149.2 U18.F6(SDRV)
NetC151_1: C151.1 R147.2 U23.B1(VS)
NetC157_1: C157.1 R146.1 R147.1 U23.D1(BUS) U23.D3(IN+)
NetC157_2: C157.2 R145.1 U23.D2(IN-)
NetD10_1: D10.1(A) R118.1
NetD13_1: D13.1(K) U18.F1(STAT)
NetD13_2: D13.2(A) R133.1
NetJ2_3: J2.3 R136.1 R137.2 U18.H7(TS)
NetR16_2: R16.2 R138.2 U18.H5(SDA)
NetR121_1: R121.1 R127.1 U19.2(OVLO)
NetR122_2: R122.2 U19.4(~{FLT})
NetR123_1: R123.1 U20.1(CLK) U21.1(~{RST})
NetR124_2: R124.2 R132.2 U21.5(TS)
NetR125_2: R125.2 U19.3(AUXOFF)
NetR126_1: R126.1 U18.F5(PROG)
NetR128_1: R128.1 R130.1 U18.F4(ILIM_HIZ)
NetR129_2: R129.2 U19.9(ILM)
NetR134_1: R134.1 U18.G7(BATP)
NetR135_1: R135.1 U18.G6(BATN)
NetR139_2: R139.2 R193.2 U18.H4(SCL)
NetR140_2: R140.2 U18.G3(~{QON})
NetR141_2: R141.2 U18.G4(~{CE})
NetR142_2: R142.2 U18.H6(IBAT)
NetR143_2: R143.2 U18.H3(~{PG})
NetR144_2: R144.2 U18.G5(~{INT})
NetS1_2: S1.2 S1.4 U21.3(PB1)
NetU19_1: U19.1(EN/UVLO) U20.5(Q)
NetU20_2: U20.2(D) U20.3(Q)

Not connected (* = marked no-connect by the designer): U23 A3(ALERT)* B2(NC)* C2(NC)*

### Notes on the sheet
- E-Fuse & Power On/Off Controller
- PROG=4.7K: 1S-Li-ion battery and switching in 750K
- VBUS range: 3.0V~5.5V
- (near U18) Recommed: IVBUS<3.3A
- Current limit=6A typ
- OV=5.484V
- (near L19) 2.2u/2.62A
- (near L19) 5x5x2
- (near J2) Battery Connector
- Default switching frequency:750KHz
- Address:0x6BH
- Default running in: Autonomous charging mode
- Top Shield Size
- 83mm
- Connector
- 2.5mm
- 31mm
- Height: 3.5mm
- 59mm
- Height: 5mm
- Bottom Shield Size
- 0
- (near U23) ADDR
- 0x40H
- Total System Power Measurement

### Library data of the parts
C125 C130 C133 C143 = CMP-0006837-2: CAP, CERM, 0.1 uF, 50 V, +/- 10%, X7R, 0603; Manufacturer: Wurth Elektronik; TaMin_C: -55°C; Polarized: N; SizeAreaWB_mm2: 4.68; Value1: Unknown; U/M: EA; Value: 0.1uF; TaMax_C: 125°C; SizeZ_mm: 1; SizeX_mm: 1.6; SizeY_mm: 0.8; SizeArea_mm2: 1.28; AEC Category: Q200
C126-C129 C142 C145 C146 = CMP-0008268-1: CAP, CERM, 10 uF, 10 V, +/- 10%, X6S, 0805; Manufacturer: MuRata; TaMin_C: -55°C; Polarized: N; SizeAreaWB_mm2: 6.75; Value1: Unknown; U/M: EA; Value: 10uF; TaMax_C: 105°C; SizeZ_mm: 1.45; SizeX_mm: 2; SizeY_mm: 1.25; Cap_Case: 0805; SizeArea_mm2: 2.5; Cap_F: 10µF; AEC Category: Q200
C131 C132 C139-C141 = CMP-0078699-1: CAP, CERM, 47 µF, 10 V,+/- 20%, X5R, 0805; Manufacturer: MuRata; TaMin_C: -55°C; Polarized: N; Green_Lifecycle: Active; SizeAreaWB_mm2: 6.75; Green_REACh: Passed; U/M: EA; Value: 47uF; TaMax_C: 85°C; SizeZ_mm: 1.45; SizeX_mm: 2; SizeY_mm: 1.25; Cap_Case: 0805; SizeArea_mm2: 2.5; AEC Category: Q200
C134 C147 = CMP-0006669-2: CAP, CERM, 0.047 uF, 25 V, +/- 10%, X7R, 0402; Manufacturer: MuRata; TaMin_C: -55°C; Polarized: N; SizeAreaWB_mm2: 3; Value1: Unknown; U/M: EA; TaMax_C: 125°C; SizeZ_mm: 0.6; SizeX_mm: 1; SizeY_mm: 0.5; Cap_F: 47nF; AEC Category: Q200
C135 C138 C148 C151 C157 = CMP-0009637-1: as C53 on sheet Sht02--Input Output Connector
C136 = CMP-0006671-2: CAP, CERM, 6800 pF, 25 V, +/- 10%, X7R, 0402; Manufacturer: MuRata; TaMin_C: -55°C; Polarized: N; SizeAreaWB_mm2: 3; Value1: Unknown; U/M: EA; Value: 6800pF; TaMax_C: 125°C; SizeZ_mm: 0.6; SizeX_mm: 1; SizeY_mm: 0.5; Cap_F: 6.8nF; AEC Category: Q200
C137 = CMP-0006607-1: as C39 on sheet Sht02--Input Output Connector
C144 = CMP-0081052-1: CAP, CERM, 4.7 µF, 16 V,+/- 10%, X5R, AEC-Q200 Grade 3, 0603; Manufacturer: MuRata; SizeAreaWB_mm2: 4.68; SizeArea_mm2: 1.28; AEC Qualified: Y; AEC Category: Q200; Value: 4.7uF; TaMax_C: 85°C; SizeZ_mm: 1; AEC Grade: 3; Polarized: N; TaMin_C: -55°C; SizeY_mm: 0.8; U/M: EA; SizeX_mm: 1.6
C149 = CMP-0080092-1: CAP, CERM, 1000 pF, 25 V,+/- 1%, C0G/NP0, 0603; Manufacturer: Kemet; Cap_F: 1nF; SizeAreaWB_mm2: 4.68; SizeArea_mm2: 1.28; AEC Qualified: N; AEC Category: Q200; Value: 1000pF; TaMax_C: 125°C; SizeZ_mm: 1; Green_REACh: Passed; TaMin_C: -55°C; SizeY_mm: 0.8; Green_Lifecycle: Active; U/M: EA; SizeX_mm: 1.6
D10 = CMP-0003041-3: LED, Amber, SMD; Manufacturer: Avago; SizeY_mm: 0.8; Vf_V: 1.9V; Value1: 0.06W; Ir_A: 100µA; Power_TotalModule: 60mW; SizeZ_mm: 0.9; SizeX_mm: 1.6; Tjmax_C: 95°C; SizeArea_mm2: 1.28; Vr_V: 5V; SizeAreaWB_mm2: 4.68; Angle: 170; Io_A: 20mA; Type: AlInGaP
D11 D12 = CMP-0084110-3: 1-Channel 30 kV ESD Protection Diode With Low Clamping Voltage in 0402 Package, DPY0002A (X1SON-2); Alternate Manufacturer: Texas Instruments; AEC Qualified: N; Rating: Catalog; SizeArea_mm2: 0.6; AEC Category: Q200; SizeAreaWB_mm2: 3.2; SizeZ_mm: 0.45; SizeX_mm: 1.0; CompType: IC
D13 = CMP-0002873-3: LED, Green, SMD; Manufacturer: Rohm; Io_A: 20mA; Value1: W; Vf_V: 2.2V; Type: AlInGaP; MFG_Status: TI_Obsolete
J2 = CMP-0076709-1: Receptacle, 2.54mm, 3x1, Gold, TH; Manufacturer: Mill-Max; Pitch_mm: 2.54; Gender: Female; CT: True; Row_Count: 1; CompType: Socket Strip; CNHeader: False
L19 = CMP-0062911-1: Inductor, Shielded, Ferrite, 2.2 uH, 2.62 A, 0.043 ohm, SMD; Manufacturer: TDK; Isat: 2.62A @ 30% inductance drop; Irms: 3.25A @ 40C rise; Green_Lifecycle: Active; SizeAreaWB_mm2: 49; DCR_ohm: 43m; Green_REACh: Passed; Value: 2.2uH; Imax_A: 2.62A; SizeZ_mm: 2; SizeX_mm: 5; SizeArea_mm2: 25; Ind_H: 2.2µH; AEC Category: Q200
R16 R132 R147 R193 = CMP-0027008-1: as R37 on sheet Sht02--Input Output Connector
R116 = CMP-0021986-1: RES, 0.02, 1%, 0.5 W, 0805; Manufacturer: Vishay-Dale; Power_W: 500mW; TempCo: 75 ppm/C; Value_Code: R020; U/M: EA; Value: 0.02; EIA_Code: E96; Res_ohm: 20m; SizeX_mm: 2.03; SizeY_mm: 1.27; SizeZ_mm: 0.635; Value2: 0.5W; SizeArea_mm2: 2.5781; AEC Qualified: N; AEC Category: Q200
R117 = CMP-0020803-2: RES, 0, 5%, 0.125 W, 0805; Manufacturer: Yageo America; Power_W: 125mW; TempCo: 200 ppm/C; Value_Code: 0000; U/M: EA; Value: 0; EIA_Code: E24; SizeX_mm: 2; SizeY_mm: 1.25; SizeZ_mm: 1.45; Value2: 0.125W; SizeArea_mm2: 2.5; VDC_V: 150V; AEC Category: Q200
R118 R133 = CMP-0026394-2: RES, 475, 1%, 0.063 W, AEC-Q200 Grade 0, 0402; Manufacturer: Vishay-Dale; Power_W: 63mW; TempCo: 100 ppm/C; Value_Code: 475R; Value: 475; EIA_Code: E96; SizeX_mm: 1; SizeY_mm: 0.5; SizeZ_mm: 0.6; Value2: 0.063W; AEC Qualified: Y; VDC_V: 50V; AEC Category: Q200; AEC Grade: 0
R121 = CMP-0027626-1: RES, 35.7 k, 1%, 0.05 W, 0201; Manufacturer: Yageo America; Power_W: 50mW; TempCo: 200 ppm/C; Value_Code: 35k7; U/M: EA; Value: 35.7k; EIA_Code: E96; SizeX_mm: 0.6; SizeY_mm: 0.3; SizeZ_mm: 0.26; Value2: 0.05W; SizeArea_mm2: 0.18; AEC Qualified: N; VDC_V: 25V; AEC Category: Q200
R122-R125 R127 R131 R138-R144 R148 R149 = CMP-0028071-1: as R38 on sheet Sht02--Input Output Connector
R126 = CMP-0028031-1: RES, 4.70 k, 1%, 0.05 W, 0201; Manufacturer: Yageo America; Power_W: 50mW; TempCo: 200 ppm/C; Value_Code: 4k70; U/M: EA; Value: 4.70k; Res_ohm: 4.7k; SizeX_mm: 0.6; SizeY_mm: 0.3; SizeZ_mm: 0.26; Value2: 0.05W; SizeArea_mm2: 0.18; AEC Qualified: N; VDC_V: 25V; AEC Category: Q200
R128 = CMP-0027332-1: RES, 127 k, 1%, 0.05 W, 0201; Manufacturer: Yageo America; Power_W: 50mW; TempCo: 200 ppm/C; U/M: EA; Value: 127k; EIA_Code: E96; SizeX_mm: 0.6; SizeY_mm: 0.3; SizeZ_mm: 0.26; Value2: 0.05W; SizeArea_mm2: 0.18; AEC Qualified: N; VDC_V: 25V; AEC Category: Q200
R129 = CMP-0026448-2: RES, 549, 1%, 0.063 W, AEC-Q200 Grade 0, 0402; Manufacturer: Vishay-Dale; Power_W: 63mW; TempCo: 100 ppm/C; Value_Code: 549R; Value: 549; EIA_Code: E96; SizeX_mm: 1; SizeY_mm: 0.5; SizeZ_mm: 0.6; Value2: 0.063W; AEC Qualified: Y; VDC_V: 50V; AEC Category: Q200; AEC Grade: 0
R130 = CMP-0027943-1: RES, 100 k, 1%, 0.05 W, 0201; Manufacturer: Yageo America; Power_W: 50mW; TempCo: 200 ppm/C; U/M: EA; Value: 100k; EIA_Code: E96; SizeX_mm: 0.6; SizeY_mm: 0.3; SizeZ_mm: 0.26; Value2: 0.05W; SizeArea_mm2: 0.18; AEC Qualified: N; VDC_V: 25V; AEC Category: Q200
R134 R135 = CMP-0026824-3: RES, 100, 5%, 0.063 W, AEC-Q200 Grade 0, 0402; Manufacturer: Vishay-Dale; Power_W: 63mW; TempCo: 200 ppm/C; Value_Code: 100R; Value: 100; EIA_Code: E24; SizeX_mm: 1; SizeY_mm: 0.5; SizeZ_mm: 0.6; Value2: 0.063W; AEC Qualified: Y; VDC_V: 50V; AEC Category: Q200; AEC Grade: 0
R136 = CMP-0027790-1: RES, 5.23 k, 1%, 0.05 W, 0201; Manufacturer: Yageo America; Power_W: 50mW; TempCo: 200 ppm/C; Value_Code: 5k23; U/M: EA; Value: 5.23k; EIA_Code: E96; SizeX_mm: 0.6; SizeY_mm: 0.3; SizeZ_mm: 0.26; Value2: 0.05W; SizeArea_mm2: 0.18; AEC Qualified: N; VDC_V: 25V; AEC Category: Q200
R137 = CMP-0027594-1: RES, 30.1 k, 1%, 0.05 W, 0201; Manufacturer: Yageo America; Power_W: 50mW; TempCo: 200 ppm/C; Value_Code: 30k1; U/M: EA; Value: 30.1k; EIA_Code: E96; SizeX_mm: 0.6; SizeY_mm: 0.3; SizeZ_mm: 0.26; Value2: 0.05W; SizeArea_mm2: 0.18; AEC Qualified: N; VDC_V: 25V; AEC Category: Q200
R145 R146 = CMP-0027946-1: RES, 10.0, 1%, 0.05 W, 0201; Manufacturer: Yageo America; Power_W: 50mW; TempCo: 350 ppm/C; Value_Code: 10R0; U/M: EA; Value: 10.0; EIA_Code: E96; Res_ohm: 10; SizeX_mm: 0.6; SizeY_mm: 0.3; SizeZ_mm: 0.26; Value2: 0.05W; SizeArea_mm2: 0.18; AEC Qualified: N; VDC_V: 25V; AEC Category: Q200
S1 = CMP-0002302-1: Switch, SPST, Off-Mom, 0.05 A, 12 VDC, SMD; Manufacturer: Wurth Elektronik; CurrentRating_mA: 50A; PositionCount: 1; SizeX_mm: 4.3; SizeY_mm: 2.9; SizeZ_mm: 1.9; SizeArea_mm2: 12.47; VDC_V: 12V; SizeAreaWB_mm2: 20.67
U18 = CMP-0085942-4: BQ25790, PREYBG0056 (DSBGA-56); Manufacturer: Texas Instruments; SizeZ_mm: 0.5; SizeArea_mm2: 10.209525; SizeAreaWB_mm2: 17.619525; AEC Category: Q200; CompType: IC; AEC Qualified: N; SizeY_mm: 3.455; SizeX_mm: 2.955
U19 = CMP-0861022-1: 23 V, 6 A, 24.5 mΩ Reverse Current Blocking eFuse with Input Reverse Polarity Protection, RPW0010A (VQFN-HR-10); Manufacturer: Texas Instruments; AEC Category: Q200; SizeArea_mm2: 4; SizeY_mm: 2; SizeAreaWB_mm2: 9; AEC Qualified: N; SizeZ_mm: 1; CompType: IC
U20 = CMP-0051481-2: Single Positive-Edge-Triggered D-Type Flip-Flop With Clear and Preset, DQE0008A, LARGE T&R; Manufacturer: Texas Instruments; Output Type: CMOS; Bits(#): 1; Input Type: CMOS/TTL; Technology Family: LVC; Schmitt Trigger: No; VCC(Max)(V): 5.5; Rating: Catalog; Output Drive (IOL/IOH)(Max)(mA): 32/-32; ICC @ Nom Voltage(Max)(mA): 0.01; VCC(Min)(V): 1.65; F @ Nom Voltage(Max)(Mhz): 150; Logic: True; Voltage(Nom)(V): 1.8,2.5,3.3,5; tpd @ Nom Voltage(Max)(ns): 13.4,7.1,5.9,4.1
U21 = CMP-0074236-1: Single Channel Push Button Controller with Configurable Delay and Reset Pulse, DRY0006A (USON-6); Alternate PartNumber: TPS3422EGDRYT; Alternate Manufacturer: Texas Instruments; SizeAreaWB_mm2: 4.9; U/M: EA; SizeZ_mm: 0.6; SizeX_mm: 1.0; SizeY_mm: 1.45; CompType: IC
U23 = CMP-0065450-1: 28-V, Bi-Directional, Zero-Drift, Low-/High-Side, I2C Out Current/Power Monitor w/ Alert in WCSP, YFF0012AKAD (DSBGA-12); Alternate PartNumber: INA231AIYFFT; Alternate Manufacturer: Texas Instruments; Green_Lifecycle: Active; SizeAreaWB_mm2: 6.313872; Green_REACh: Passed; U/M: EA; SizeZ_mm: 0.625; SizeX_mm: 1.388; SizeY_mm: 1.644; SizeArea_mm2: 2.281872; CompType: IC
